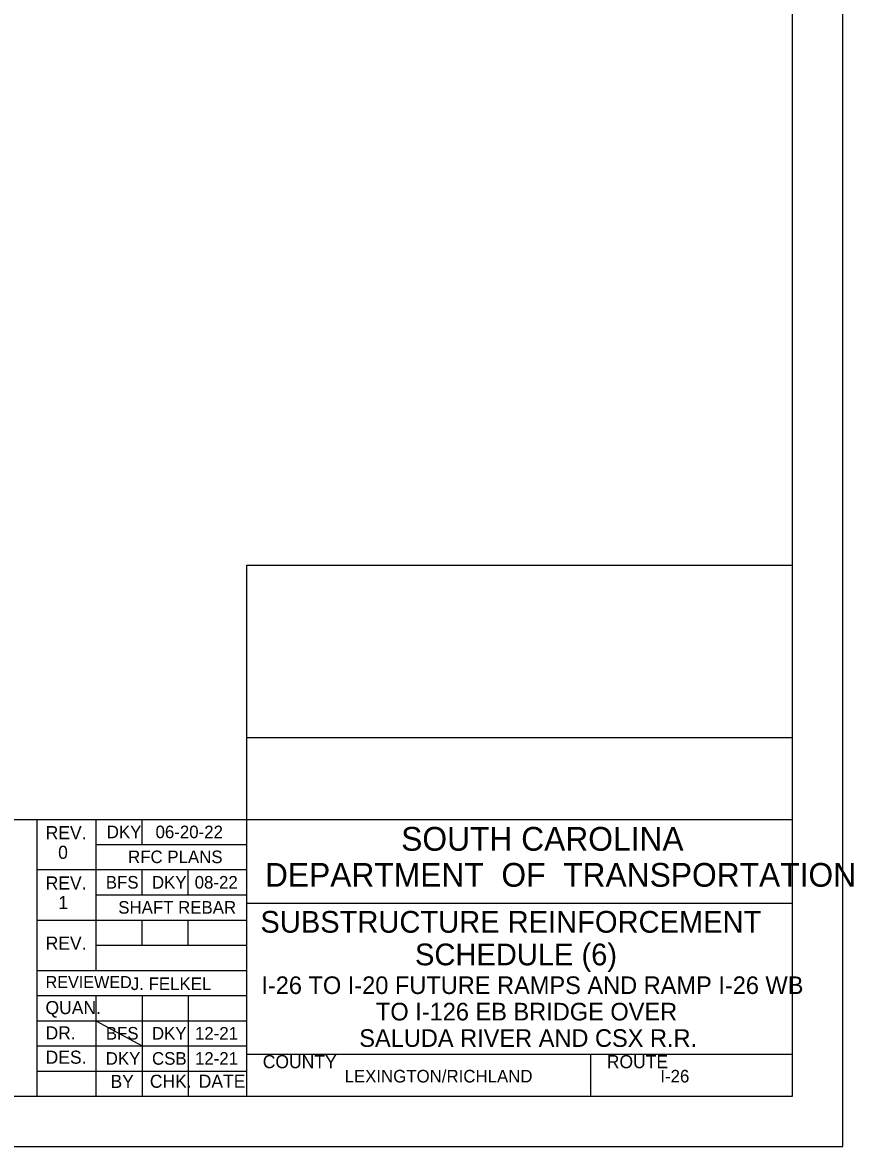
# Model space of a CAD drawing. Extents: x -121.2 to -24.9, y 6.4 to 65.9.
# Drawn here: x -46.88 to -24.88, y 6.35 to 36.13 of the extents above; entities that cross this region are included whole.
import ezdxf

# ---------------------------------------------------------------- set-up
doc = ezdxf.new("R2010")
doc.units = 0
for name, color, linetype in [('BR_BORDER LINES', 7, 'Continuous'), ('BR_TEXT', 7, 'Continuous'), ('Level 31', 7, 'Continuous')]:
    doc.layers.add(name, color=color, linetype=linetype)

msp = doc.modelspace()

# ---------------------------------------------------------------- linework, layer by layer
at = {"layer": 'BR_BORDER LINES'}
for p, q in [((-26.496, 7.683), (-26.496, 63.683)), ((-40.941, 7.683), (-40.941, 21.754)), ((-40.941, 21.754), (-26.496, 21.754)), ((-40.94, 17.182), (-26.496, 17.182)), ((-60.804, 15.017), (-46.496, 15.017)), ((-46.496, 7.683), (-46.496, 15.017)), ((-46.496, 15.017), (-26.496, 15.017)), ((-44.941, 15.017), (-44.941, 11.017)), ((-43.718, 14.35), (-43.718, 15.017)), ((-44.941, 14.35), (-40.941, 14.35)), ((-46.496, 13.684), (-40.941, 13.684)), ((-43.718, 13.017), (-43.718, 13.684)), ((-42.496, 13.017), (-42.496, 13.684)), ((-44.941, 13.017), (-40.941, 13.017)), ((-40.941, 12.795), (-40.941, 12.795)), ((-40.941, 12.795), (-26.495, 12.795)), ((-46.496, 12.35), (-40.941, 12.35)), ((-43.718, 11.684), (-43.718, 12.35)), ((-42.496, 11.684), (-42.496, 12.35)), ((-44.941, 11.684), (-40.941, 11.684)), ((-46.496, 11.017), (-40.941, 11.017)), ((-46.496, 10.35), (-40.941, 10.35)), ((-44.941, 10.35), (-44.941, 7.683)), ((-43.718, 10.35), (-43.718, 7.683)), ((-42.496, 10.35), (-42.496, 7.683)), ((-46.496, 9.683), (-40.941, 9.683)), ((-46.496, 9.017), (-40.941, 9.017)), ((-40.941, 8.795), (-26.496, 8.795)), ((-40.68, 8.795), (-26.496, 8.795)), ((-31.829, 7.683), (-31.829, 8.795)), ((-46.496, 8.35), (-40.941, 8.35)), ((-116.272, 7.683), (-26.496, 7.683))]:
    msp.add_line(p, q, dxfattribs=at)
at = {"layer": 'Level 31'}
for p, q in [((-33.717, 11.621), (-33.717, 11.621)), ((-44.941, 9.683), (-43.718, 9.017))]:
    msp.add_line(p, q, dxfattribs=at)
msp.add_lwpolyline([(-121.161, 6.35), (-25.161, 6.35), (-25.161, 65.017), (-121.161, 65.017)], close=True, dxfattribs=at)

# ---------------------------------------------------------------- texts
at = {"layer": 'BR_TEXT'}
for s, height, p in [('REV.', 0.3467, (-46.27, 14.491)), ('DKY', 0.3333, (-44.652, 14.517)), ('06-20-22', 0.3333, (-43.36, 14.517)), ('SOUTH CAROLINA', 0.62899, (-36.855, 14.186)), ('0', 0.347, (-45.94, 13.971)), ('RFC PLANS', 0.3333, (-44.087, 13.857)), ('DEPARTMENT  OF  TRANSPORTATION', 0.62899, (-40.463, 13.232)), ('REV.', 0.3467, (-46.27, 13.158)), ('BFS', 0.3333, (-44.677, 13.183)), ('DKY', 0.3333, (-43.456, 13.183)), ('08-22', 0.3333, (-42.324, 13.183)), ('1', 0.347, (-45.935, 12.638)), ('SHAFT REBAR', 0.33333, (-44.347, 12.519)), ('SUBSTRUCTURE REINFORCEMENT', 0.576, (-40.583, 12.014)), ('REV.', 0.3467, (-46.27, 11.565)), ('SCHEDULE (6)', 0.576, (-36.489, 11.15)), ('REVIEWED', 0.32, (-46.272, 10.546)), ('J. FELKEL', 0.3333, (-44.015, 10.495)), ('I-26 TO I-20 FUTURE RAMPS AND RAMP I-26 WB', 0.46667, (-40.558, 10.39)), ('QUAN.', 0.3467, (-46.274, 9.857)), ('TO I-126 EB BRIDGE OVER', 0.46667, (-37.523, 9.69)), ('DR.', 0.3467, (-46.273, 9.186)), ('BFS', 0.3333, (-44.677, 9.183)), ('DKY', 0.3333, (-43.456, 9.183)), ('12-21', 0.3333, (-42.316, 9.183)), ('SALUDA RIVER AND CSX R.R.', 0.46667, (-37.965, 8.99)), ('DES.', 0.3467, (-46.271, 8.543)), ('DKY', 0.3333, (-44.679, 8.517)), ('CSB', 0.3333, (-43.454, 8.517)), ('12-21', 0.3333, (-42.316, 8.517)), ('COUNTY', 0.3467, (-40.521, 8.425)), ('ROUTE', 0.3467, (-31.41, 8.425)), ('LEXINGTON/RICHLAND', 0.33332, (-38.355, 8.047)), ('I-26', 0.3333, (-29.993, 8.047)), ('BY', 0.3467, (-44.553, 7.902)), ('CHK.', 0.3467, (-43.511, 7.906)), ('DATE', 0.3467, (-42.217, 7.906))]:
    msp.add_text(s, height=height, dxfattribs=at).set_placement(p)

doc.saveas('drawing.dxf')
